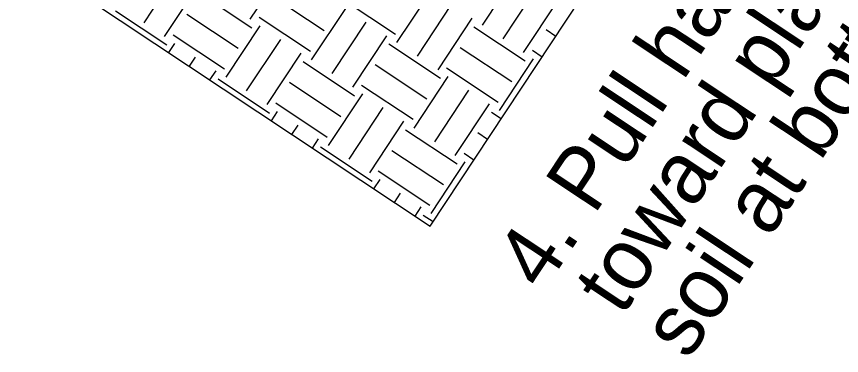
# Model space of a CAD drawing. Extents: x 561231 to 564240, y 590260 to 602519.
# Drawn here: x 563607.97 to 563657.68, y 590671.93 to 590692.34 of the extents above; entities that cross this region are included whole.
import ezdxf

# ---------------------------------------------------------------- set-up
doc = ezdxf.new("R2010")
doc.units = 0
doc.layers.add('Old_Level_1', color=7, linetype='Continuous')

msp = doc.modelspace()

# ---------------------------------------------------------------- linework, layer by layer
at = {"layer": 'Old_Level_1'}
for p, q in [((563632.887, 590679.722), (563657.335, 590716.579)), ((563607.969, 590696.252), (563632.887, 590679.722)), ((563622.053, 590692.176), (563624.181, 590695.385)), ((563615.655, 590691.955), (563617.712, 590695.056)), ((563636.044, 590691.825), (563638.1, 590694.925)), ((563616.896, 590691.133), (563618.952, 590694.233)), ((563630.887, 590690.781), (563632.943, 590693.881)), ((563637.284, 590691.002), (563639.341, 590694.103)), ((563619.057, 590693.717), (563622.157, 590691.661)), ((563623.406, 590693.544), (563626.507, 590691.488)), ((563627.704, 590693.339), (563630.804, 590691.283)), ((563638.524, 590690.18), (563640.581, 590693.28)), ((563625.752, 590689.723), (563627.808, 590692.823)), ((563632.127, 590689.958), (563634.184, 590693.059)), ((563613.937, 590692.682), (563617.037, 590690.626)), ((563618.235, 590692.477), (563621.335, 590690.421)), ((563622.584, 590692.304), (563625.684, 590690.248)), ((563620.595, 590688.679), (563622.652, 590691.78)), ((563626.992, 590688.9), (563629.048, 590692.001)), ((563633.367, 590689.136), (563635.424, 590692.237)), ((563635.528, 590691.721), (563638.629, 590689.664)), ((563639.878, 590691.547), (563640.47, 590691.154)), ((563617.412, 590691.237), (563620.512, 590689.181)), ((563621.835, 590687.856), (563623.892, 590690.957)), ((563628.232, 590688.078), (563630.289, 590691.178)), ((563617.146, 590690.164), (563617.516, 590690.721)), ((563630.408, 590690.685), (563633.509, 590688.629)), ((563634.705, 590690.48), (563637.806, 590688.424)), ((563639.055, 590690.307), (563639.647, 590689.914)), ((563618.386, 590689.341), (563618.756, 590689.899)), ((563623.075, 590687.034), (563625.131, 590690.135)), ((563637.066, 590686.682), (563639.122, 590689.783)), ((563625.236, 590689.619), (563628.336, 590687.562)), ((563629.586, 590689.445), (563632.686, 590687.389)), ((563619.626, 590688.518), (563619.996, 590689.076)), ((563633.883, 590689.24), (563636.983, 590687.184)), ((563620.116, 590688.583), (563623.216, 590686.527)), ((563624.413, 590688.378), (563627.514, 590686.322)), ((563631.931, 590685.624), (563633.987, 590688.725)), ((563628.763, 590688.205), (563631.863, 590686.148)), ((563633.171, 590684.802), (563635.227, 590687.902)), ((563626.774, 590684.58), (563628.831, 590687.681)), ((563623.591, 590687.138), (563626.691, 590685.082)), ((563628.014, 590683.758), (563630.071, 590686.858)), ((563634.411, 590683.979), (563636.468, 590687.079)), ((563623.325, 590686.065), (563623.695, 590686.623)), ((563636.587, 590686.587), (563637.179, 590686.194)), ((563624.565, 590685.242), (563624.935, 590685.8)), ((563629.254, 590682.935), (563631.311, 590686.035)), ((563631.415, 590685.52), (563634.515, 590683.463)), ((563635.765, 590685.347), (563636.357, 590684.954)), ((563625.805, 590684.42), (563626.175, 590684.977)), ((563626.295, 590684.485), (563629.395, 590682.428)), ((563630.592, 590684.28), (563633.693, 590682.223)), ((563634.942, 590684.107), (563635.534, 590683.714)), ((563632.953, 590680.482), (563635.009, 590683.582)), ((563629.77, 590683.04), (563632.87, 590680.983)), ((563629.504, 590681.966), (563629.874, 590682.524)), ((563630.744, 590681.144), (563631.114, 590681.701)), ((563631.984, 590680.321), (563632.354, 590680.879)), ((563632.474, 590680.386), (563633.066, 590679.993))]:
    msp.add_line(p, q, dxfattribs=at)

# ---------------------------------------------------------------- texts
for s, p in [(' toward planter, firming ', (563643.698, 590673.076)), ('4. Pull handle of bar ', (563639.712, 590675.72)), (' soil at bottom.', (563647.684, 590670.432))]:
    msp.add_text(s, height=3.72047, rotation=56.4424, dxfattribs=at).set_placement(p)

doc.saveas('drawing.dxf')
